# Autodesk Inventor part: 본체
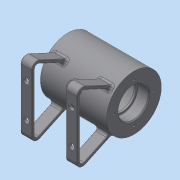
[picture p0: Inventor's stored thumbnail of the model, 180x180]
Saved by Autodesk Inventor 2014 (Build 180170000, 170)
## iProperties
Created: 2021-12
Part Number: 본체
Material: 일반
Document SubType Name: Modeling
Designer: dg
Density: 1 g/cm^3
Appearance: 기본값
Author: dg
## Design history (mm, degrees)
sketch "스케치1"
  geometry: L1 (0, 0)-(70, 0); L2 (70, 0)-(70, 29); L3 (70, 29)-(0, 29); L4 (0, 29)-(0, 0); L5 (0, 16)-(12, 16); L6 (12, 16)-(12, 14); L7 (12, 14)-(14, 14); L8 (14, 14)-(14, 21); L9 (14, 21)-(56, 21); L10 (56, 21)-(56, 14); L11 (56, 14)-(58, 14); L12 (58, 14)-(58, 16); L13 (58, 16)-(70, 16)
  constraints: 26 end point, 8 parallel, 3 perpendicular, 2 collinear, 2 horizontal alignment, 2 point on line, 1 horizontal
  dimensions: "d0" = 70 distance of L1.start L1.end; "d1" = 29 distance between parallel lines of L1 L3; "d2" = 16 distance between parallel lines of L1 L5; "d3" = 21 distance between parallel lines of L1 L9; "d4" = 14 distance between parallel lines of L1 L7; "d5" = 42 distance of L8.end L9.end; "d6" = 12 distance of L5.start L5.end; "d7" = 2 distance of L6.end L7.end
revolve "회전1" sketch "스케치1" stored, may be unused: angle "d8" = 90 deg
fillet "모깎기1" dims "d9" = 3
chamfer "모따기1" distance "d10" = 1; stored, may be unused: second distance "d11" = 2, angle "d12" = 45 deg
chamfer "모따기2" distance "d13" = 1; stored, may be unused: second distance "d14" = 2, angle "d15" = 45 deg
fillet "모깎기2" dims "d16" = 0.3
node "작업 평면2"
  node "작업 평면1"
sketch "스케치2"
  geometry: L1 (-6, -29)-(-6, 29) reference; C1 r 5 at (29, 0); 2 further points
  constraints: 1 centre point, 1 coincident, 1 horizontal alignment
  dimensions: "d19" = 35 distance from line of L1 point (29, 0); "d20" = 10 diameter of C1
extrude "돌출1" join sketch "스케치2" stored distance "d21" = 10; taper "d22" = 0 deg
hole "구멍1" diameter "d25" = 5.188; stored, may be unused: countersink angle "d29" = 90 deg, drill point angle "d31" = 118 deg; dims "d23" = 10, "d24" = 10, "d26" = 6, "d27" = 4, "d28" = 2, "d30" = 8
sketch "스케치3"
  geometry: C1 r 5 at (0, 0) reference; C2 r 1.5 at (0, 0); 1 further point
  constraints: 1 centre point, 1 coincident
  dimensions: "d32" = 3 diameter of C2
extrude "돌출2" cut sketch "스케치3" stored distance "d33" = 10; taper "d34" = 0 deg
fillet "모깎기3" dims "d35" = 1
node "작업 평면3"
sketch "스케치4"
  geometry: L1 (-22.743, -17.993)-(-40, -55); L2 (-40, -55)-(40, -55); L3 (40, -55)-(22.743, -17.993); L4 (20.574, -20.438)-(35.291, -52); L5 (35.291, -52)-(-35.291, -52); L6 (-35.291, -52)-(-20.574, -20.438); A1 r 29 centre (0, 0) between (-20.574, -20.438) and (-22.743, -17.993) reference; 2 further points
  constraints: 12 end point, 4 point on circle, 1 horizontal, 1 midpoint, 1 vertical alignment
  dimensions: "d37" = 80 distance of L2.end L1.end; "d38" = 55 distance from line of L2 point (0, 0); "d39" = 65 deg angle of L2 L1; "d40" = 65 deg angle of L2 L3; "d41" = 3 distance between parallel lines of L1 L6; "d42" = 3 distance between parallel lines of L3 L4; "d43" = 3 distance between parallel lines of L5 L2
extrude "돌출3" join sketch "스케치4" distance "d44" = 12; taper "d45" = 0 deg
node "작업 평면4"
fillet "모깎기4" dims "d46" = 6
fillet "모깎기5" dims "d47" = 3
fillet "모깎기6" dims "d48" = 0.5
fillet "모깎기7" dims "d49" = 3
fillet "모깎기8" dims "d50" = 6
sketch "스케치5"
  geometry: L1 (-0.5, 0)-(-0.5, -61.164) reference; C1 r 3 at (5.5, -12.582); C2 r 3 at (5.5, -48.582); 1 further point
  constraints: 2 centre point, 1 vertical alignment
  dimensions: "d51" = 6 diameter of C1; "d52" = 6 diameter of C2; "d53" = 6 distance from line of L1 C1.centre; "d54" = 36 distance of C2.centre C1.centre; "d55" = 18 vertical distance of point (-5.5, -30.582) C1.centre
extrude "돌출4" cut sketch "스케치5" distance "d56" = 12; taper "d57" = 0 deg
node "작업 평면5"
node "작업 평면6"
sketch "스케치6"
  geometry: L1 (0, 0)-(0, -46.155); L2 (0, 0)-(13.052, -35.861); L3 (15.342, -24.609)-(16.583, -28.018); L4 (16.583, -28.018)-(5.306, -32.122); L5 (5.306, -32.122)-(4.066, -28.714); A1 r 29 centre (0, 0) between (15.342, -24.609) and (4.066, -28.714) reference
  constraints: 10 end point, 2 perpendicular, 2 point on circle, 1 parallel, 1 vertical
  dimensions: "d58" = 20 deg angle of L1 L2; "d59" = 32 distance from line of A1.centre L4; "d61" = 6 distance between parallel lines of L2 L3; "d62" = 12 distance between parallel lines of L3 L5
extrude "돌출5" join sketch "스케치6" stored distance "d63" = 12; taper "d64" = 0 deg
fillet "모깎기9" dims "d65" = 6
hole "구멍2" diameter "d68" = 5.188; stored, may be unused: countersink angle "d72" = 90 deg, drill point angle "d74" = 118 deg; dims "d69" = 6, "d70" = 4, "d71" = 2, "d73" = 8, "d94" = 10, "d95" = 10
fillet "모깎기10" dims "d75" = 1
sketch "스케치7"
  geometry: C1 r 29 at (0, 0) reference; 1 further point
  constraints: 1 vertical alignment
  dimensions: "d76" = 21 distance of C1.centre point (0, 21)
hole "구멍3" sketch "스케치7" at (0, 21) diameter "d77" = 2.459; stored, may be unused: countersink angle "d81" = 90 deg, drill point angle "d83" = 118 deg; dims "d78" = 8, "d79" = 4, "d80" = 2, "d82" = 10
node "작업 평면7"
node "작업축2"
node "작업 평면9"
  node "작업 평면8"
node "작업 평면10"
node "작업 평면11"
node "작업 평면12"
node "작업 평면13"
sketch "스케치8"
  geometry: L1 (35, 29)-(-35, 29) reference; L2 (-35, 29)-(-35, -29) reference; 3 further points
  constraints: 1 horizontal alignment, 1 midpoint, 1 vertical alignment, 1 other
  dimensions: "d90" = 35 distance from line of point (0, 0) L2 (derived); "d91" = 29 distance from line of point (0, 0) L1 (derived)
feature "엠보싱1" sketch "스케치8" dims "d92" = 0.5, "d93" = 0
node "솔리드1"
mirror "대칭1"
mirror "대칭2"
pattern_circular "원형 패턴1" dims angle "d85" = 360 deg
mirror "대칭3"
node "작업축1"
other parameters: "d17" = 0, "d18" = 32, "d36" = -5, "d87" = 0, "d88" = 0, "d89" = 180 deg
